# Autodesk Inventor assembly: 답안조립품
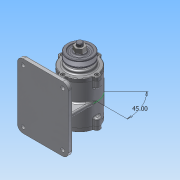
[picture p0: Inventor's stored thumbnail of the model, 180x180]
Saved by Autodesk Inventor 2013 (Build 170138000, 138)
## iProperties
Created: 2015-12
Part Number: 답안조립품
Document SubType Name: Assembly
Designer: user-11
Author: user-11
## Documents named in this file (11)
- C:\Users\user-11\Desktop\451207V1008\답안조립품.iam
- C:\Users\user-11\Desktop\451207V1008\1-본체.ipt
- C:\Users\user-11\Desktop\451207V1008\커버.ipt
- C:\Users\user-11\Desktop\451207V1008\커버2.ipt
- C:\Users\user-11\Desktop\451207V1008\볼트 M4 x 12.ipt
- C:\Users\user-11\Desktop\451207V1008\베어링 6204.ipt
- C:\Users\user-11\Desktop\451207V1008\축.ipt
- C:\Users\user-11\Desktop\451207V1008\키(4 x 4 x 12).ipt
- C:\Users\user-11\Desktop\451207V1008\V-벨트풀리.ipt
- C:\Users\user-11\Desktop\451207V1008\오일실.ipt
- C:\Users\user-11\Desktop\451207V1008\너트 M12x1.25.ipt
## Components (7 placed, 6 different names)
1. 1-본체:1
2. KS B 2023 6204 - 20 x 47 x 14:1
3. KS B 2023 6204 - 20 x 47 x 14:2
4. KS B 1311 (I) 4 x 4 x 12:1 — 각도:1, 각도:2
5. V-벨트풀리:1 — 각도:2
6. KS B 2804 D D - 20 32 8:1
7. KS B 1012 클래스 1 일반 - 미터 M12x1.25:1
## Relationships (2: Angle 2)
- 각도:1 [Angle]: KS B 1311 (I) 4 x 4 x 12:1
- 각도:2 [Angle]: KS B 1311 (I) 4 x 4 x 12:1 ↔ V-벨트풀리:1
